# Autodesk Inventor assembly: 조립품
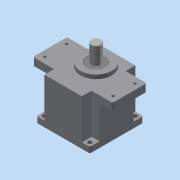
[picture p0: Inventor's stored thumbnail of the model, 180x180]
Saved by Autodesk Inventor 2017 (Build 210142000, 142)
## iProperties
Part Number: 조립품
Material: 일반
Document SubType Name: Assembly
Designer: user
Author: user
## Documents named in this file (10)
- C:\Users\user\Desktop\700116V1009\조립품.iam
- C:\Users\user\Desktop\700116V1009\메인 축.ipt
- C:\Users\user\Desktop\700116V1009\베어링 608.ipt
- C:\Users\user\Desktop\700116V1009\베어링 6003.ipt
- C:\Users\user\Desktop\700116V1009\본체.ipt
- C:\Users\user\Desktop\700116V1009\볼트 M4.ipt
- C:\Users\user\Desktop\700116V1009\서브 축.ipt
- C:\Users\user\Desktop\700116V1009\오일 실 8 22 7.ipt
- C:\Users\user\Desktop\700116V1009\오일 실 17 32 8.ipt
- C:\Users\user\Desktop\700116V1009\커버.ipt
